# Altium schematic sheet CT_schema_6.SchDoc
size 274 x 160 mm
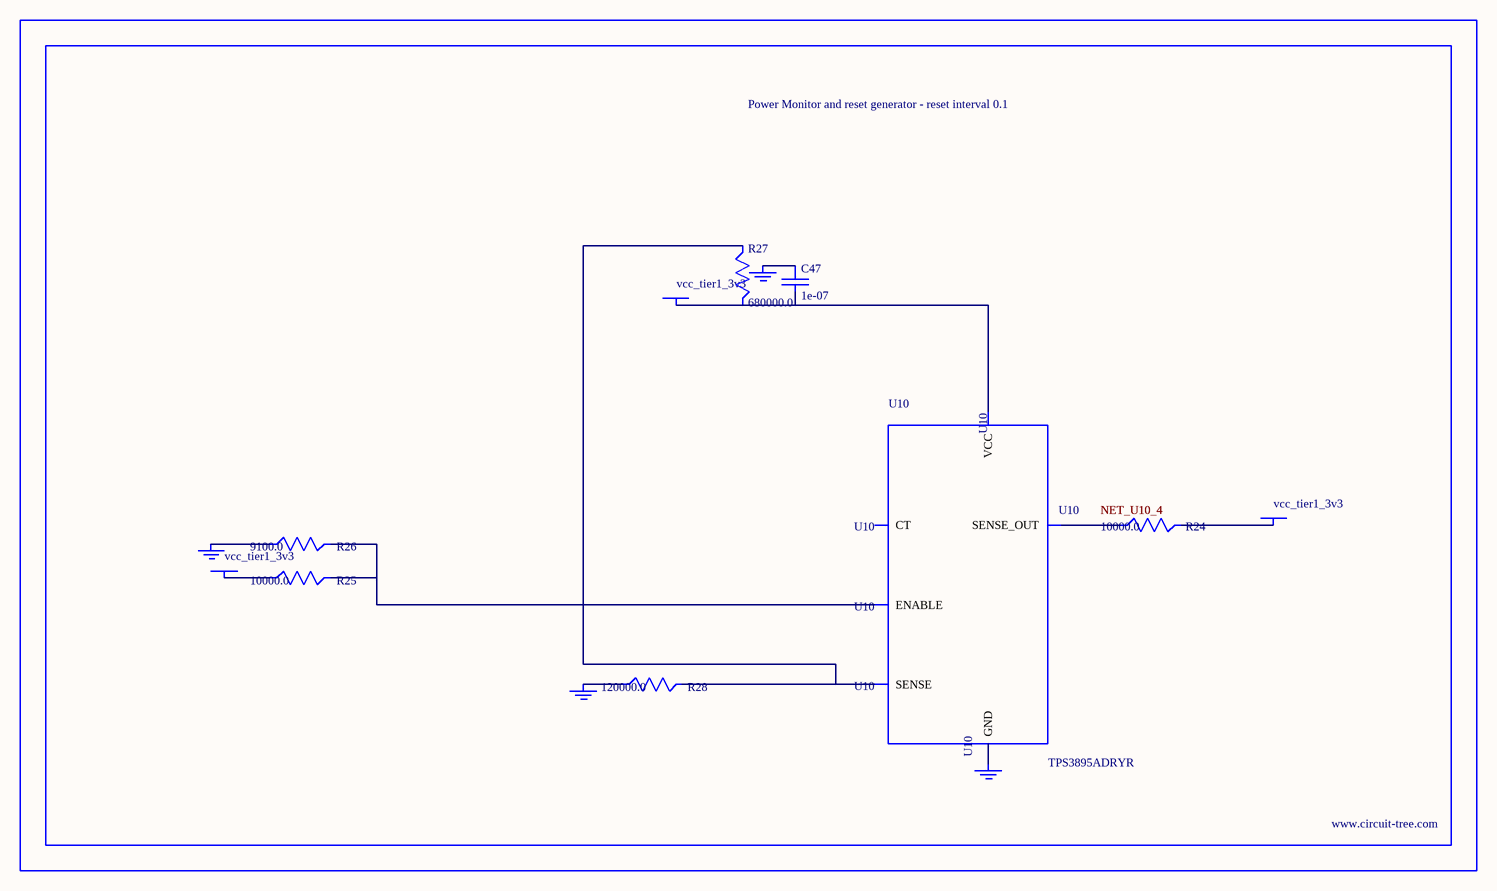
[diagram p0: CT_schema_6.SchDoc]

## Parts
BORDER5  (no value)
C47  1e-07  [C0402]
GND_INSTANCE_5_0  (no value)
GND_INSTANCE_5_1  (no value)
GND_INSTANCE_5_2  (no value)
GND_INSTANCE_5_3  (no value)
POWER_INSTANCE_5_0  vcc_tier1_3v3
POWER_INSTANCE_5_1  vcc_tier1_3v3
POWER_INSTANCE_5_2  vcc_tier1_3v3
R24  10000.0  [R0603]
R25  10000.0  [R0603]
R26  9100.0  [R0603]
R27  680000.0  [R0603]
R28  120000.0  [R0603]
U10  TPS3895ADRYR  [SON-6]

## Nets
NetC47_1: C47.1 GND_INSTANCE_5_2.0(GND)
NetC47_2: C47.2 POWER_INSTANCE_5_2.0(PWR) R27.2 U10.6(VCC)
NetGND_INSTANCE_5_0_0: GND_INSTANCE_5_0.0(GND) R26.1
NetGND_INSTANCE_5_1_0: GND_INSTANCE_5_1.0(GND) R28.1
NetGND_INSTANCE_5_3_0: GND_INSTANCE_5_3.0(GND) U10.2(GND)
NetPOWER_INSTANCE_5_0_0: POWER_INSTANCE_5_0.0(PWR) R25.1
NetPOWER_INSTANCE_5_1_0: POWER_INSTANCE_5_1.0(PWR) R24.2
NetR24_1: R24.1 U10.4(SENSE_OUT)
NetR25_2: R25.2 R26.2 U10.1(ENABLE)
NetR27_1: R27.1 R28.2 U10.3(SENSE)

Not connected (* = marked no-connect by the designer): U10 5(CT)

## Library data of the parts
BORDER5 = BORDER_PAGE5
C47 = C0402C104K3RACTU
GND_INSTANCE_5_0-GND_INSTANCE_5_3 = GND
POWER_INSTANCE_5_0-POWER_INSTANCE_5_2 = PWR
R24 R25 = RC0603JR-0710KL
R26 = RC0603JR-079K1L
R27 = RC0603JR-07680KL
R28 = RC0603JR-07120KL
